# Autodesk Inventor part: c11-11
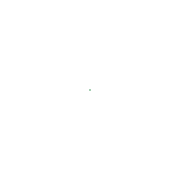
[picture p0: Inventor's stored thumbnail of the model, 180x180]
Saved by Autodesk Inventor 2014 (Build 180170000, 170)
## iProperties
Created: 2011-01
Part Number: c11-11
Material: Steel, Mild
Document SubType Name: Sheet Metal
Designer: Thom Tremblay
Density: 7.86 g/cm^3
Sheet Metal Rule: Steel - 16ga
Appearance: Nylon 6
Author: Thom Tremblay
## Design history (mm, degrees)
sketch "Sketch1"
  geometry: 1 further point
other parameters: "Thickness" = 1.524 (derived), "BendRadius" = 1.524 (= Thickness), "BendReliefWidth" = 1.524 (= Thickness), "BendReliefDepth" = 0.762 (= 0.5 x Thickness), "CornerReliefSize" = 6.096 (= 4 x Thickness), "SeamGap" = 0.01, "MinimumRemnant" = 3.048 (= 2 x Thickness), "TransitionRadius" = 1.524 (= BendRadius), "JacobiRadiusSize" = 1.524 (= BendRadius), "GapSize" = 0.762 (= 0.5 x Thickness)
